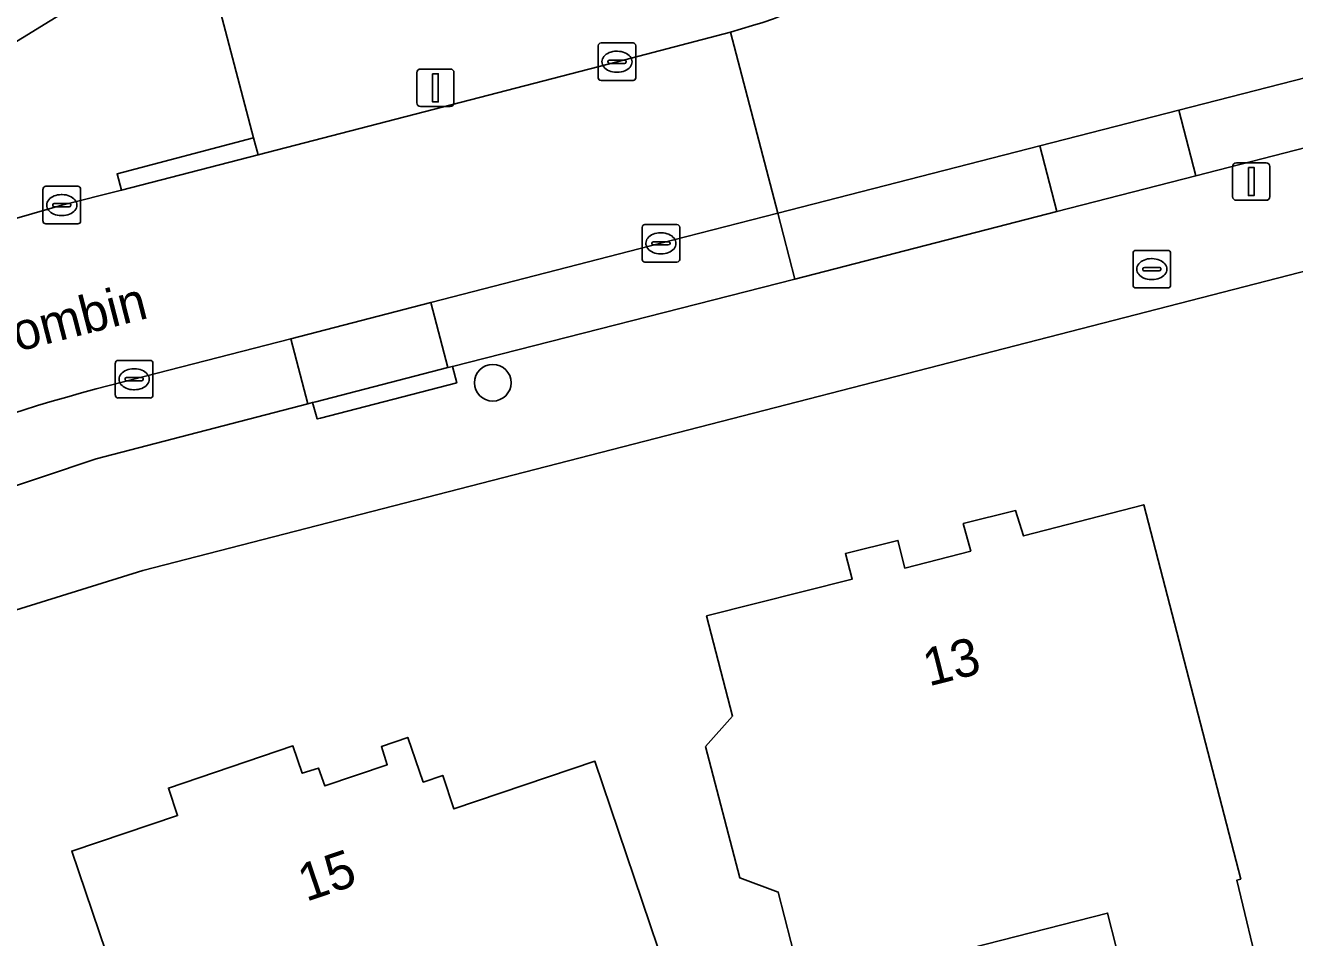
# Model space of a CAD drawing. Extents: x 158835 to 160077, y 386387 to 387778.
# Drawn here: x 159412.85 to 159446.64, y 386690.72 to 386715 of the extents above; entities that cross this region are included whole.
import ezdxf

# ---------------------------------------------------------------- set-up
doc = ezdxf.new("R2010")
doc.units = 0
for name, color, linetype in [('IMGEO_Boom', 7, 'Continuous'), ('IMGEO_Brandkraan', 7, 'Continuous'), ('IMGEO_Erf', 7, 'Continuous'), ('IMGEO_Groenvoorziening', 7, 'Continuous'), ('IMGEO_Kolk', 7, 'Continuous'), ('IMGEO_Lichtmast', 7, 'Continuous'), ('IMGEO_Openbare_ruimte_label', 7, 'Continuous'), ('IMGEO_Pand', 7, 'Continuous'), ('IMGEO_Pand_nummerreeks', 7, 'Continuous'), ('IMGEO_Parkeervlak_open', 7, 'Continuous'), ('IMGEO_Rijbaan_lokaal_open', 7, 'Continuous'), ('IMGEO_Voetpad_open', 7, 'Continuous')]:
    doc.layers.add(name, color=color, linetype=linetype)

msp = doc.modelspace()

# ---------------------------------------------------------------- linework, layer by layer
at = {"layer": 'IMGEO_Boom'}
msp.add_circle((159425.294, 386705.49), 0.489, dxfattribs=at)
at = {"layer": 'IMGEO_Brandkraan'}
for p, q in [((159442.341, 386708.088), (159442.341, 386708.94)), ((159442.416, 386709.014), (159443.268, 386709.014)), ((159442.829, 386708.794), (159442.854, 386708.794)), ((159443.342, 386708.94), (159443.342, 386708.088)), ((159442.6, 386708.508), (159442.6, 386708.52)), ((159443.038, 386708.471), (159442.64, 386708.471)), ((159442.643, 386708.557), (159443.041, 386708.557)), ((159443.084, 386708.52), (159443.084, 386708.508)), ((159442.852, 386708.234), (159442.827, 386708.234)), ((159443.268, 386708.014), (159442.416, 386708.014))]:
    msp.add_line(p, q, dxfattribs=at)
for points in [[(159442.341, 386708.088), (159442.341, 386708.94)], [(159442.416, 386709.014), (159443.268, 386709.014)], [(159443.342, 386708.94), (159443.342, 386708.088)], [(159443.268, 386708.014), (159442.416, 386708.014)]]:
    msp.add_lwpolyline(points, dxfattribs=at)
for centre, radius, start, end in [((159442.418, 386708.938), 0.0765, 91.552, 178.448), ((159442.418, 386708.938), 0.0765, 91.552, 178.448), ((159443.266, 386708.938), 0.0765, 1.552, 88.448), ((159443.266, 386708.938), 0.0765, 1.552, 88.448), ((159442.64, 386708.517), 0.0403, 85.8775, 175.7526), ((159442.637, 386708.507), 0.0366, 178.938, 274.7102), ((159443.041, 386708.514), 0.043, 264.8664, 352.4533), ((159443.045, 386708.519), 0.0386, 1.7309, 96.639), ((159442.418, 386708.09), 0.0765, 181.552, 268.448), ((159442.418, 386708.09), 0.0765, 181.552, 268.448), ((159443.266, 386708.09), 0.0765, 271.552, 358.448), ((159443.266, 386708.09), 0.0765, 271.552, 358.448)]:
    msp.add_arc(centre, radius, start, end, dxfattribs=at)
for centre, major_axis, ratio, start_param, end_param in [((159442.828, 386708.514), (-0.387, 0.002), 0.722429, 4.712389, 7.853982), ((159442.853, 386708.514), (-0.39, 0.002), 0.717154, 1.570796, 4.712389)]:
    msp.add_ellipse(centre, major_axis=major_axis, ratio=ratio, start_param=start_param, end_param=end_param, dxfattribs=at)
at = {"layer": 'IMGEO_Erf'}
for points in [[(159320.416, 386657.723), (159398.233, 386705.745), (159432.071, 386726.541), (159426.546, 386739.026), (159422.284, 386748.699), (159421.725, 386750), (159419.683, 386754.749), (159414.254, 386767.377)], [(159500, 386722.142), (159452.288, 386709.846), (159415.977, 386700.489), (159412.19, 386699.306), (159408.523, 386697.788), (159405.088, 386695.997), (159404.197, 386695.456), (159329.763, 386649.508)]]:
    msp.add_lwpolyline(points, dxfattribs=at)
for points in [[(159431.87, 386692.307), (159430.96, 386695.804), (159431.678, 386696.61), (159430.988, 386699.283), (159434.867, 386700.263), (159434.686, 386700.941), (159436.081, 386701.29), (159436.265, 386700.553), (159438.019, 386701.001), (159437.822, 386701.738), (159439.214, 386702.086), (159439.425, 386701.412), (159442.627, 386702.241), (159445.208, 386692.27), (159445.101, 386692.244), (159445.737, 386689.62), (159442.324, 386688.758), (159441.665, 386691.368), (159433.564, 386689.301), (159432.894, 386691.928)], [(159429.1, 386677.074), (159427.164, 386682.822), (159425.387, 386682.223), (159424.062, 386686.156), (159418.125, 386684.157), (159418.437, 386683.23), (159414.49, 386681.912), (159413.076, 386686.06), (159416.091, 386687.1), (159414.083, 386693.021), (159416.904, 386693.965), (159416.659, 386694.695), (159419.974, 386695.821), (159420.222, 386695.092), (159420.651, 386695.23), (159420.819, 386694.754), (159422.486, 386695.317), (159422.33, 386695.803), (159423.029, 386696.046), (159423.443, 386694.858), (159423.961, 386695.033), (159424.262, 386694.142), (159428.016, 386695.412), (159433.68, 386678.642)]]:
    msp.add_lwpolyline(points, close=True, dxfattribs=at)
at = {"layer": 'IMGEO_Groenvoorziening'}
for points in [[(159434.338, 386725.824), (159432.664, 386724.796), (159417.947, 386715.735), (159418.927, 386712.01)], [(159431.628, 386714.826), (159432.207, 386715.004)], [(159419.05, 386711.558), (159428.604, 386714.035), (159431.628, 386714.826)], [(159418.927, 386712.01), (159419.05, 386711.558)]]:
    msp.add_lwpolyline(points, dxfattribs=at)
msp.add_arc((159430.915, 386720.219), 5.372, 283.9105, 22.6074, dxfattribs=at)
at = {"layer": 'IMGEO_Kolk'}
for p, q in [((159428.177, 386714.536), (159429.029, 386714.536)), ((159428.102, 386713.61), (159428.102, 386714.462)), ((159428.59, 386714.316), (159428.615, 386714.316)), ((159429.103, 386714.462), (159429.103, 386713.61)), ((159428.361, 386714.03), (159428.361, 386714.042)), ((159428.799, 386713.993), (159428.401, 386713.993)), ((159428.404, 386714.079), (159428.802, 386714.079)), ((159428.845, 386714.042), (159428.845, 386714.03)), ((159429.029, 386713.536), (159428.177, 386713.536)), ((159428.613, 386713.756), (159428.588, 386713.756)), ((159413.319, 386709.793), (159413.319, 386710.645)), ((159413.394, 386710.719), (159414.246, 386710.719)), ((159413.807, 386710.499), (159413.832, 386710.499)), ((159414.32, 386710.645), (159414.32, 386709.793)), ((159413.578, 386710.213), (159413.578, 386710.225)), ((159414.016, 386710.176), (159413.618, 386710.176)), ((159413.621, 386710.262), (159414.019, 386710.262)), ((159414.062, 386710.225), (159414.062, 386710.213)), ((159413.83, 386709.939), (159413.805, 386709.939)), ((159414.246, 386709.719), (159413.394, 386709.719)), ((159429.271, 386708.774), (159429.271, 386709.626)), ((159429.346, 386709.7), (159430.198, 386709.7)), ((159429.759, 386709.48), (159429.784, 386709.48)), ((159430.272, 386709.626), (159430.272, 386708.774)), ((159429.53, 386709.194), (159429.53, 386709.206)), ((159429.968, 386709.157), (159429.57, 386709.157)), ((159429.573, 386709.243), (159429.971, 386709.243)), ((159430.014, 386709.206), (159430.014, 386709.194)), ((159429.782, 386708.92), (159429.757, 386708.92)), ((159430.198, 386708.7), (159429.346, 386708.7)), ((159415.32, 386706.083), (159416.172, 386706.083)), ((159415.245, 386705.157), (159415.245, 386706.009)), ((159415.733, 386705.863), (159415.758, 386705.863)), ((159416.246, 386706.009), (159416.246, 386705.157)), ((159415.504, 386705.577), (159415.504, 386705.589)), ((159415.942, 386705.54), (159415.544, 386705.54)), ((159415.547, 386705.626), (159415.945, 386705.626)), ((159415.988, 386705.589), (159415.988, 386705.577)), ((159416.172, 386705.083), (159415.32, 386705.083)), ((159415.756, 386705.303), (159415.731, 386705.303))]:
    msp.add_line(p, q, dxfattribs=at)
for points in [[(159428.177, 386714.536), (159429.029, 386714.536)], [(159428.102, 386713.61), (159428.102, 386714.462)], [(159429.103, 386714.462), (159429.103, 386713.61)], [(159429.029, 386713.536), (159428.177, 386713.536)], [(159413.319, 386709.793), (159413.319, 386710.645)], [(159413.394, 386710.719), (159414.246, 386710.719)], [(159414.32, 386710.645), (159414.32, 386709.793)], [(159414.246, 386709.719), (159413.394, 386709.719)], [(159429.271, 386708.774), (159429.271, 386709.626)], [(159429.346, 386709.7), (159430.198, 386709.7)], [(159430.272, 386709.626), (159430.272, 386708.774)], [(159430.198, 386708.7), (159429.346, 386708.7)], [(159415.32, 386706.083), (159416.172, 386706.083)], [(159415.245, 386705.157), (159415.245, 386706.009)], [(159416.246, 386706.009), (159416.246, 386705.157)], [(159416.172, 386705.083), (159415.32, 386705.083)]]:
    msp.add_lwpolyline(points, dxfattribs=at)
for centre, radius, start, end in [((159428.179, 386714.46), 0.0765, 91.552, 178.448), ((159428.179, 386714.46), 0.0765, 91.552, 178.448), ((159429.027, 386714.46), 0.0765, 1.552, 88.448), ((159429.027, 386714.46), 0.0765, 1.552, 88.448), ((159428.401, 386714.039), 0.0403, 85.8775, 175.7526), ((159428.398, 386714.029), 0.0366, 178.938, 274.7102), ((159428.802, 386714.036), 0.043, 264.8664, 352.4533), ((159428.806, 386714.041), 0.0386, 1.7309, 96.639), ((159428.179, 386713.612), 0.0765, 181.552, 268.448), ((159428.179, 386713.612), 0.0765, 181.552, 268.448), ((159429.027, 386713.612), 0.0765, 271.552, 358.448), ((159429.027, 386713.612), 0.0765, 271.552, 358.448), ((159413.396, 386710.643), 0.0765, 91.552, 178.448), ((159413.396, 386710.643), 0.0765, 91.552, 178.448), ((159414.244, 386710.643), 0.0765, 1.552, 88.448), ((159414.244, 386710.643), 0.0765, 1.552, 88.448), ((159413.618, 386710.222), 0.0403, 85.8775, 175.7526), ((159413.615, 386710.212), 0.0366, 178.938, 274.7102), ((159414.019, 386710.219), 0.043, 264.8664, 352.4533), ((159414.023, 386710.224), 0.0386, 1.7309, 96.639), ((159413.396, 386709.795), 0.0765, 181.552, 268.448), ((159413.396, 386709.795), 0.0765, 181.552, 268.448), ((159414.244, 386709.795), 0.0765, 271.552, 358.448), ((159414.244, 386709.795), 0.0765, 271.552, 358.448), ((159429.348, 386709.624), 0.0765, 91.552, 178.448), ((159429.348, 386709.624), 0.0765, 91.552, 178.448), ((159430.196, 386709.624), 0.0765, 1.552, 88.448), ((159430.196, 386709.624), 0.0765, 1.552, 88.448), ((159429.57, 386709.203), 0.0403, 85.8775, 175.7526), ((159429.567, 386709.193), 0.0366, 178.938, 274.7102), ((159429.971, 386709.2), 0.043, 264.8664, 352.4533), ((159429.975, 386709.205), 0.0386, 1.7309, 96.639), ((159429.348, 386708.776), 0.0765, 181.552, 268.448), ((159429.348, 386708.776), 0.0765, 181.552, 268.448), ((159430.196, 386708.776), 0.0765, 271.552, 358.448), ((159430.196, 386708.776), 0.0765, 271.552, 358.448), ((159415.322, 386706.007), 0.0765, 91.552, 178.448), ((159415.322, 386706.007), 0.0765, 91.552, 178.448), ((159416.17, 386706.007), 0.0765, 1.552, 88.448), ((159416.17, 386706.007), 0.0765, 1.552, 88.448), ((159415.544, 386705.586), 0.0403, 85.8775, 175.7526), ((159415.541, 386705.576), 0.0366, 178.938, 274.7102), ((159415.945, 386705.583), 0.043, 264.8664, 352.4533), ((159415.949, 386705.588), 0.0386, 1.7309, 96.639), ((159415.322, 386705.159), 0.0765, 181.552, 268.448), ((159415.322, 386705.159), 0.0765, 181.552, 268.448), ((159416.17, 386705.159), 0.0765, 271.552, 358.448), ((159416.17, 386705.159), 0.0765, 271.552, 358.448)]:
    msp.add_arc(centre, radius, start, end, dxfattribs=at)
for centre, major_axis, ratio, start_param, end_param in [((159428.589, 386714.036), (-0.387, 0.002), 0.722429, 4.712389, 7.853982), ((159428.614, 386714.036), (-0.39, 0.002), 0.717154, 1.570796, 4.712389), ((159413.806, 386710.219), (-0.387, 0.002), 0.722429, 4.712389, 7.853982), ((159413.831, 386710.219), (-0.39, 0.002), 0.717154, 1.570796, 4.712389), ((159429.758, 386709.2), (-0.387, 0.002), 0.722429, 4.712389, 7.853982), ((159429.783, 386709.2), (-0.39, 0.002), 0.717154, 1.570796, 4.712389), ((159415.732, 386705.583), (-0.387, 0.002), 0.722429, 4.712389, 7.853982), ((159415.757, 386705.583), (-0.39, 0.002), 0.717154, 1.570796, 4.712389)]:
    msp.add_ellipse(centre, major_axis=major_axis, ratio=ratio, start_param=start_param, end_param=end_param, dxfattribs=at)
at = {"layer": 'IMGEO_Lichtmast'}
for p, q in [((159423.272, 386712.942), (159423.272, 386713.742)), ((159423.272, 386713.742), (159423.272, 386712.942)), ((159423.372, 386713.842), (159424.162, 386713.842)), ((159424.162, 386713.842), (159423.372, 386713.842)), ((159424.262, 386713.742), (159424.262, 386712.942)), ((159424.262, 386712.942), (159424.262, 386713.742)), ((159424.162, 386712.842), (159423.372, 386712.842)), ((159423.372, 386712.842), (159424.162, 386712.842)), ((159444.994, 386710.446), (159444.994, 386711.246)), ((159444.994, 386711.246), (159444.994, 386710.446)), ((159445.094, 386711.346), (159445.884, 386711.346)), ((159445.884, 386711.346), (159445.094, 386711.346)), ((159445.984, 386711.246), (159445.984, 386710.446)), ((159445.984, 386710.446), (159445.984, 386711.246)), ((159445.884, 386710.346), (159445.094, 386710.346)), ((159445.094, 386710.346), (159445.884, 386710.346))]:
    msp.add_line(p, q, dxfattribs=at)
for points in [[(159423.692, 386713.717), (159423.842, 386713.717), (159423.842, 386712.967), (159423.692, 386712.967), (159423.692, 386713.717)], [(159445.414, 386711.221), (159445.564, 386711.221), (159445.564, 386710.471), (159445.414, 386710.471), (159445.414, 386711.221)]]:
    msp.add_lwpolyline(points, dxfattribs=at)
for centre, start, end in [((159423.372, 386713.742), 90, 180), ((159423.372, 386713.742), 90, 180), ((159424.162, 386713.742), 0, 90), ((159424.162, 386713.742), 360, 90), ((159423.372, 386712.942), 180, 270), ((159423.372, 386712.942), 180, 270), ((159424.162, 386712.942), 270, 0), ((159424.162, 386712.942), 270, 0), ((159445.094, 386711.246), 90, 180), ((159445.094, 386711.246), 90, 180), ((159445.884, 386711.246), 0, 90), ((159445.884, 386711.246), 360, 90), ((159445.094, 386710.446), 180, 270), ((159445.094, 386710.446), 180, 270), ((159445.884, 386710.446), 270, 0), ((159445.884, 386710.446), 270, 0)]:
    msp.add_arc(centre, 0.1, start, end, dxfattribs=at)
at = {"layer": 'IMGEO_Pand'}
for points in [[(159434.686, 386700.941), (159434.867, 386700.263), (159430.988, 386699.283), (159431.678, 386696.61), (159430.96, 386695.804), (159431.87, 386692.307), (159432.894, 386691.928), (159433.564, 386689.301), (159441.665, 386691.368), (159442.324, 386688.758), (159445.737, 386689.62), (159445.101, 386692.244), (159445.208, 386692.27), (159442.627, 386702.241), (159439.425, 386701.412), (159439.214, 386702.086), (159437.822, 386701.738), (159438.019, 386701.001), (159436.265, 386700.553), (159436.081, 386701.29)], [(159420.222, 386695.092), (159419.974, 386695.821), (159416.659, 386694.695), (159416.904, 386693.965), (159414.083, 386693.021), (159416.091, 386687.1), (159413.076, 386686.06), (159414.49, 386681.912), (159418.437, 386683.23), (159418.125, 386684.157), (159424.062, 386686.156), (159425.387, 386682.223), (159427.164, 386682.822), (159429.1, 386677.074), (159433.68, 386678.642), (159428.016, 386695.412), (159424.262, 386694.142), (159423.961, 386695.033), (159423.443, 386694.858), (159423.029, 386696.046), (159422.33, 386695.803), (159422.486, 386695.317), (159420.819, 386694.754), (159420.651, 386695.23)]]:
    msp.add_lwpolyline(points, close=True, dxfattribs=at)
at = {"layer": 'IMGEO_Parkeervlak_open'}
for points in [[(159450.489, 386712.668), (159450.032, 386714.409), (159443.561, 386712.745), (159444.01, 386710.999)], [(159440.313, 386710.047), (159439.864, 386711.795), (159432.881, 386710), (159433.336, 386708.25)], [(159432.881, 386710), (159429.772, 386709.201), (159423.648, 386707.623), (159424.096, 386705.891), (159424.221, 386705.923), (159433.336, 386708.25)]]:
    msp.add_lwpolyline(points, close=True, dxfattribs=at)
for points in [[(159420.367, 386704.925), (159419.918, 386706.661), (159414.732, 386705.324)], [(159402.794, 386700.406), (159400.977, 386699.298), (159400.9, 386699.252), (159401.816, 386697.7), (159401.946, 386697.78), (159403.659, 386698.835), (159406.135, 386700.142), (159410.36, 386701.997), (159414.734, 386703.467), (159420.367, 386704.925)]]:
    msp.add_lwpolyline(points, dxfattribs=at)
msp.add_arc((159427.739, 386656.803), 50.234, 105.0062, 119.7734, dxfattribs=at)
at = {"layer": 'IMGEO_Rijbaan_lokaal_open'}
for points in [[(159432.207, 386715.004), (159431.628, 386714.826), (159432.881, 386710), (159439.864, 386711.795), (159443.561, 386712.745), (159450.032, 386714.409), (159448.769, 386719.226)], [(159414.732, 386705.324), (159419.918, 386706.661), (159423.648, 386707.623), (159429.772, 386709.201), (159432.881, 386710), (159431.628, 386714.826), (159428.604, 386714.035), (159419.05, 386711.558), (159415.406, 386710.621), (159413.821, 386710.218), (159412.625, 386709.875), (159409.062, 386708.73), (159404.723, 386706.975), (159400.559, 386704.84), (159399.143, 386704.002), (159396.4, 386702.289), (159393.65, 386700.585), (159390.447, 386698.628), (159384.513, 386694.951), (159377.211, 386690.406), (159373.987, 386688.446), (159361.298, 386680.617), (159358.099, 386678.643), (159353.058, 386675.561)]]:
    msp.add_lwpolyline(points, dxfattribs=at)
for centre, radius, start, end in [((159430.915, 386720.219), 5.372, 283.9105, 22.6074), ((159427.739, 386656.803), 50.234, 105.0062, 119.7734)]:
    msp.add_arc(centre, radius, start, end, dxfattribs=at)
at = {"layer": 'IMGEO_Voetpad_open'}
for points in [[(159412.625, 386709.875), (159413.821, 386710.218), (159415.406, 386710.621), (159415.291, 386711.051), (159418.927, 386712.01), (159417.947, 386715.735), (159432.664, 386724.796), (159434.338, 386725.824), (159433.727, 386727.236), (159433.61, 386727.506), (159432.071, 386726.541), (159398.233, 386705.745)], [(159404.197, 386695.456), (159405.088, 386695.997), (159408.523, 386697.788), (159412.19, 386699.306), (159415.977, 386700.489), (159452.288, 386709.846), (159500, 386722.142)], [(159479.208, 386720.08), (159463.438, 386716.024), (159463.303, 386715.988), (159463.416, 386715.558), (159459.86, 386714.637), (159459.751, 386715.054), (159451.443, 386712.914), (159450.489, 386712.668), (159444.01, 386710.999), (159440.313, 386710.047), (159433.336, 386708.25), (159424.221, 386705.923), (159424.334, 386705.489), (159420.707, 386704.548), (159420.621, 386704.526), (159420.496, 386704.959), (159420.367, 386704.925), (159414.734, 386703.467), (159410.36, 386701.997)]]:
    msp.add_lwpolyline(points, dxfattribs=at)
for points in [[(159443.561, 386712.745), (159439.864, 386711.795), (159440.313, 386710.047), (159444.01, 386710.999)], [(159418.927, 386712.01), (159415.291, 386711.051), (159415.406, 386710.621), (159419.05, 386711.558)], [(159423.648, 386707.623), (159419.918, 386706.661), (159420.367, 386704.925), (159420.496, 386704.959), (159420.582, 386704.981), (159424.096, 386705.891)], [(159424.334, 386705.489), (159424.221, 386705.923), (159424.096, 386705.891), (159420.582, 386704.981), (159420.496, 386704.959), (159420.621, 386704.526), (159420.707, 386704.548)]]:
    msp.add_lwpolyline(points, close=True, dxfattribs=at)

# ---------------------------------------------------------------- texts
at = {"layer": 'IMGEO_Openbare_ruimte_label'}
msp.add_text('Grand Combin', height=1, rotation=14.481, dxfattribs=at).set_placement((159407.742, 386705.047))
at = {"layer": 'IMGEO_Pand_nummerreeks'}
for s, rotation, p in [('13', 14.2596, (159436.903, 386697.401)), ('15', 18.7655, (159420.325, 386691.664))]:
    msp.add_text(s, height=1, rotation=rotation, dxfattribs=at).set_placement(p)

doc.saveas('drawing.dxf')
